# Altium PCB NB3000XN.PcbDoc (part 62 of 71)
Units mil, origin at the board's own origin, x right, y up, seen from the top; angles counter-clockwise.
Board outline 9527.56 x 6929.77 mil, 6 copper layers (Top Layer, GND+SHIELD, MidLayer1, MidLayer2, P2 - 3V3+5V0, Bottom Layer), stack 62.375 mil thick; 832 components, 1027 nets, 4655 pads, 4981 vias.
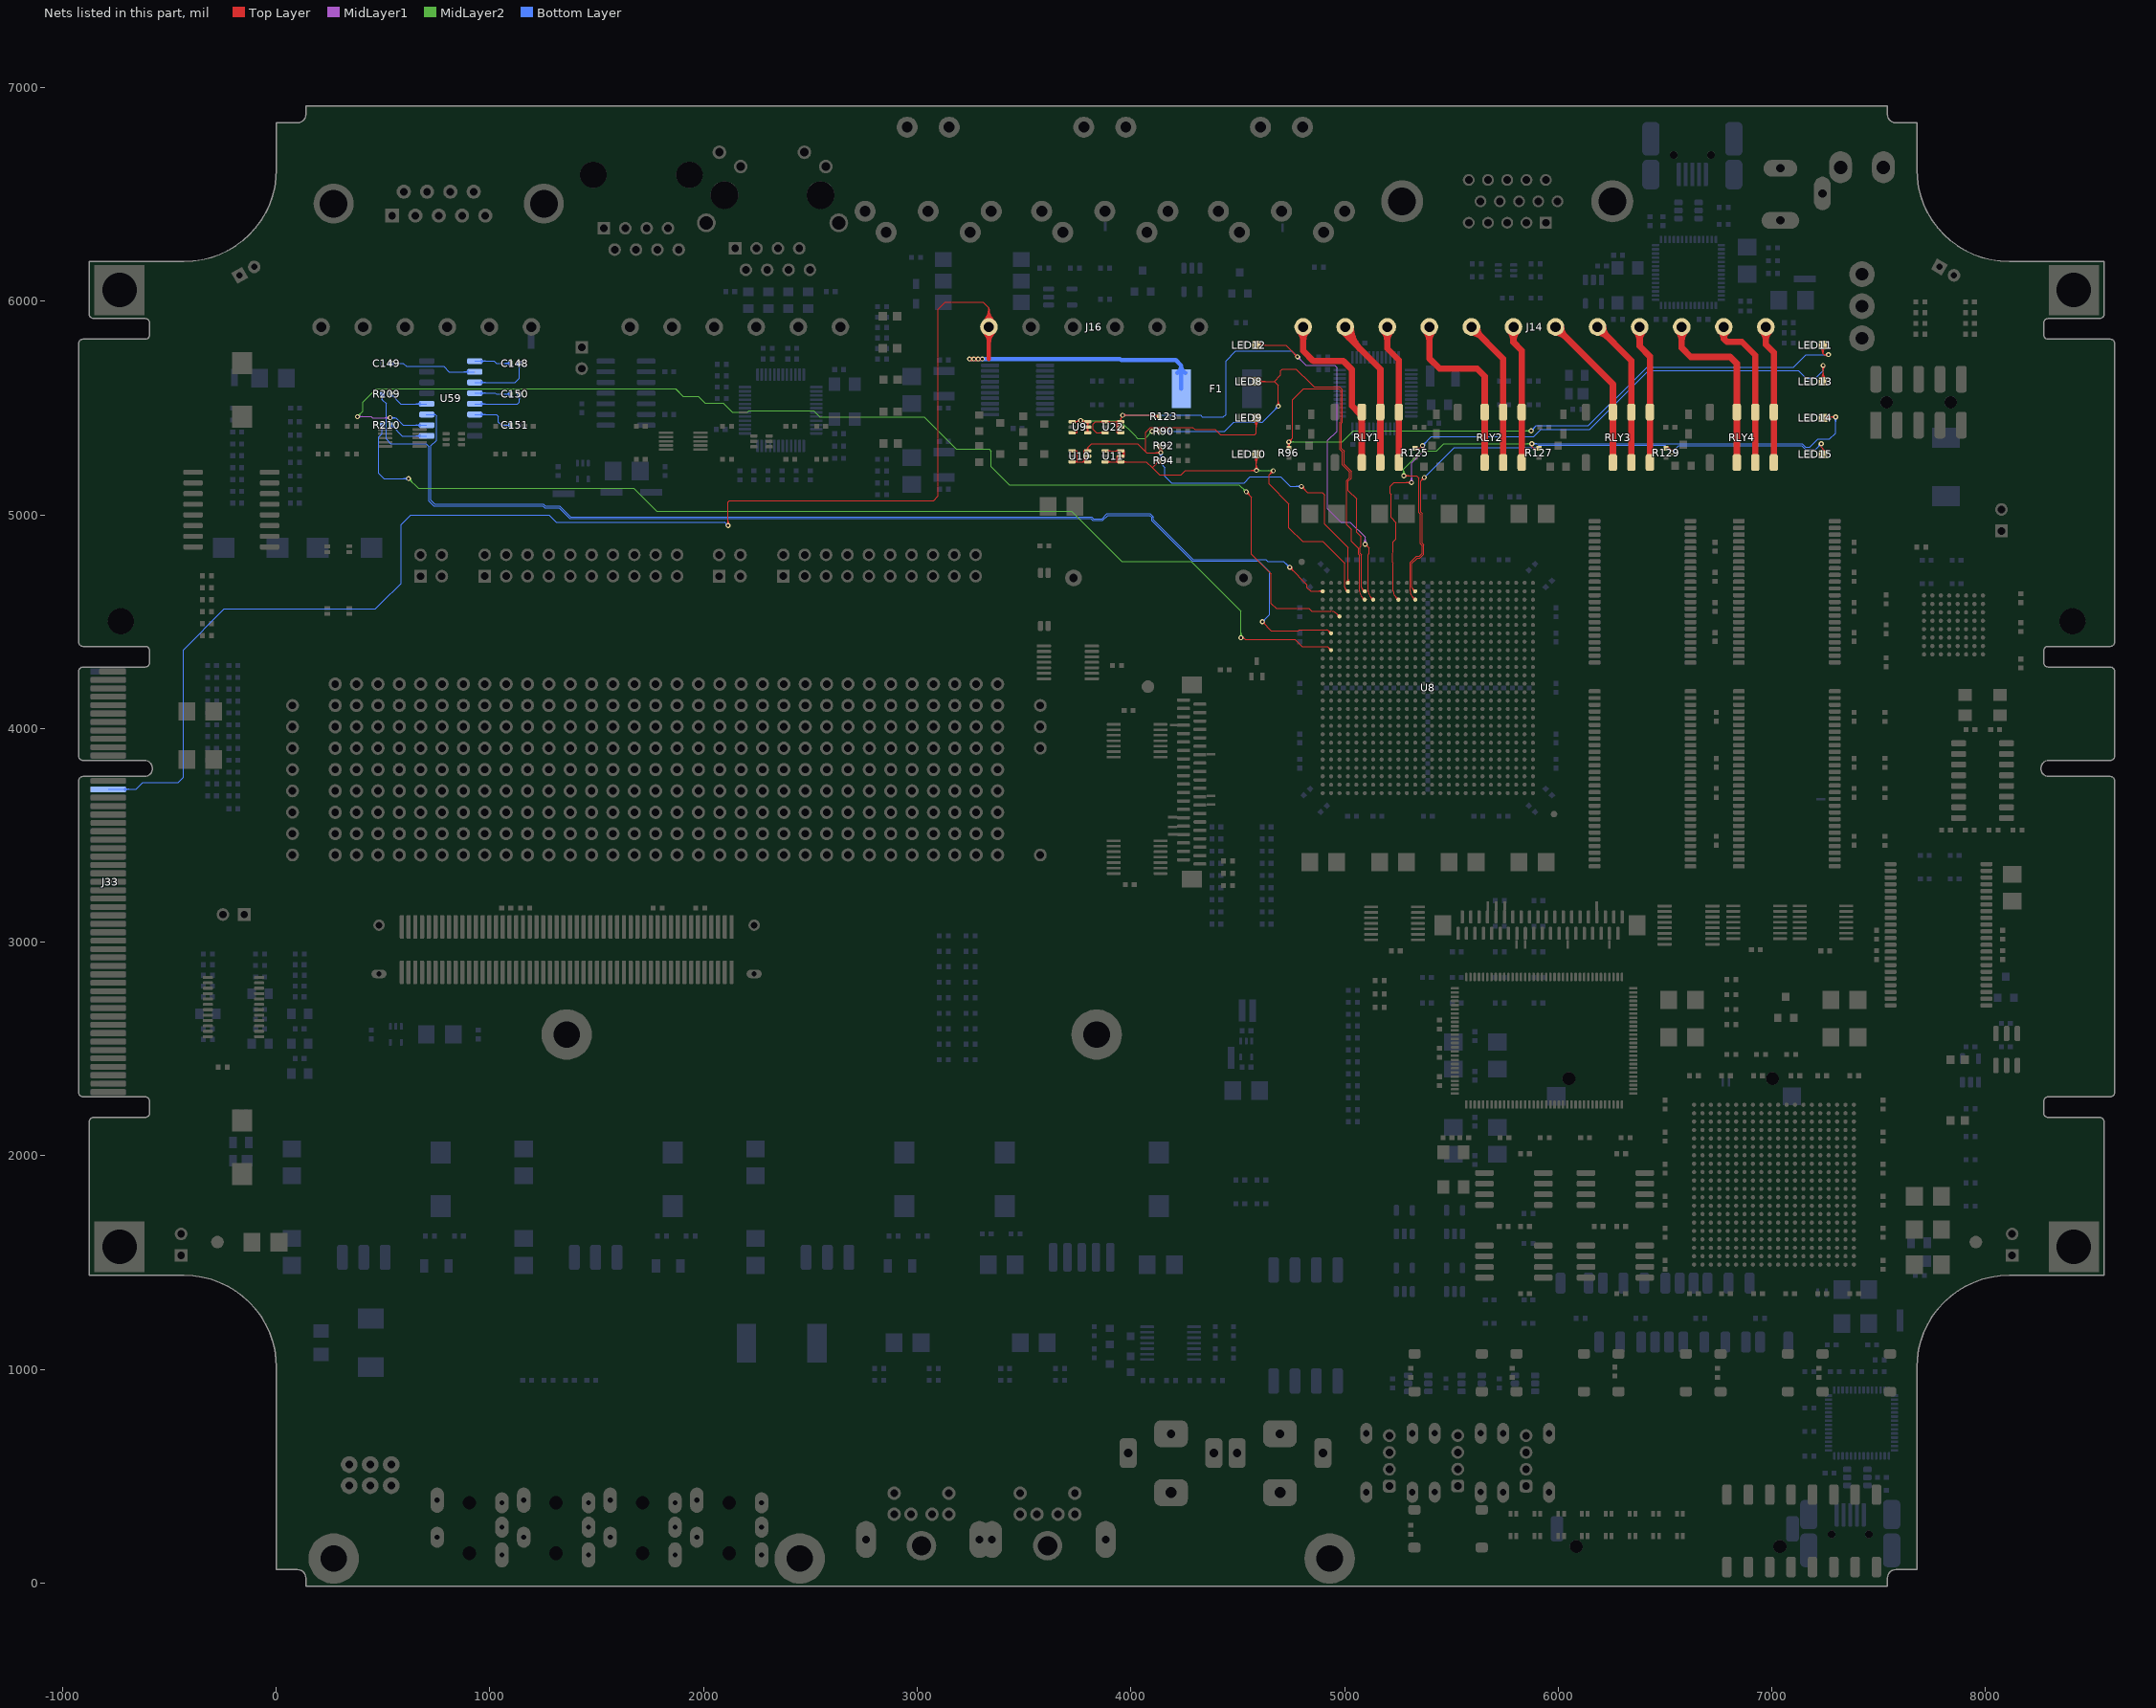
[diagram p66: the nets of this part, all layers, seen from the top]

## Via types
v1: diameter 23, hole 11.81, Top Layer to Bottom Layer, 3672 vias
v2: diameter 26, hole 11.81, Top Layer to Bottom Layer, 461 vias
v3: diameter 19, hole 11.81, Top Layer to Bottom Layer, tented both sides, 396 vias
v4: diameter 23.62, hole 11.81, Top Layer to Bottom Layer, 288 vias
v5: diameter 20, hole 11.81, Top Layer to Bottom Layer, 91 vias
v6: diameter 23, hole 11.81, Top Layer to Bottom Layer, tented both sides, 50 vias
v7: diameter 31, hole 11.81, Top Layer to Bottom Layer, 15 vias
v8: diameter 27.56, hole 11.81, Top Layer to Bottom Layer, tented both sides, 4 vias
v9: diameter 29, hole 11.81, Top Layer to Bottom Layer, 3 vias
v10: diameter 21, hole 11.81, Top Layer to Bottom Layer, 1 vias

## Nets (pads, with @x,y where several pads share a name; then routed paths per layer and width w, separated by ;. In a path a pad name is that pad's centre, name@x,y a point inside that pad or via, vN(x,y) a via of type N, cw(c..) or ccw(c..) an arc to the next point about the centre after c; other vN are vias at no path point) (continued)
PWM.PWM0: LED12.1 R123.1 U8.C7 U22.1 U22.3 U22.4 U22.5 U22.6 | length 4491.4
  Top Layer w4: U22.3@3866.99,5380.85 ccw(c3856.96,5370.82) 3856.96,5385 ccw(c3856.96,5399.18) U22.3@3866.99,5389.15 ; U22.1@3866.99,5432.03 ccw(c3856.96,5422) 3856.96,5436.18 ccw(c3856.96,5450.36) U22.1@3866.99,5440.33 ; U22.3@3880,5385 3839.23,5385 3823.52,5400.71 3823.52,5425.04 3834.66,5436.18 U22.1@3880,5436.18 3936.02,5436.18 ; U22.1@3893.01,5432.03 cw(c3903.04,5422) 3903.04,5436.18 cw(c3903.04,5450.36) U22.1@3893.01,5440.33 ; 3936.02,5383.79 cw(c3963.03,5383.79) U22.5@3947.38,5405.8 ; 3936.02,5388.38 ccw(c3946.19,5388.38) U22.4@3940.62,5379.88 ; 3936.02,5391.55 cw(c3957.52,5391.55) U22.5@3945.06,5409.06 ; 3936.02,5395.78 ccw(c3951.04,5395.78) U22.4@3942.81,5383.22 ; 3936.02,5399.3 cw(c3952.01,5399.3) U22.5@3942.74,5412.32 ; 3936.02,5403.19 ccw(c3955.89,5403.19) U22.4@3945,5386.57 ; 3936.02,5407.05 cw(c3946.49,5407.05) U22.5@3940.43,5415.58 ; 3936.02,5409.38 cw(c3963.03,5409.38) U22.6@3947.38,5431.39 ; 3936.02,5413.97 ccw(c3946.19,5413.97) U22.5@3940.62,5405.47 ; 3936.02,5417.14 cw(c3957.52,5417.14) U22.6@3945.06,5434.65 ; 3936.02,5421.37 ccw(c3951.04,5421.37) U22.5@3942.81,5408.81 ; 3936.02,5424.89 cw(c3952.01,5424.89) U22.6@3942.74,5437.91 ; 3936.02,5428.78 ccw(c3955.89,5428.78) U22.5@3945,5412.16 ; 3936.02,5432.64 cw(c3946.49,5432.64) U22.6@3940.43,5441.17 ; U22.4@3938.36,5383.27 ccw(c3936.02,5382.55) 3936.02,5385 ; U22.4@3938.36,5386.73 cw(c3936.02,5387.45) 3936.02,5385 ; U22.6@3939.82,5432.03 ccw(c3929.8,5422) 3929.8,5436.18 ccw(c3929.79,5450.36) U22.6@3939.82,5440.33 ; U22.4@3947.2,5389.91 cw(c3960.74,5410.59) 3936.02,5410.59 ; U22.5@3947.2,5415.5 cw(c3960.74,5436.18) 3936.02,5436.18 ; U22.6@3948.68,5440.33 ccw(c3938.65,5450.36) 3952.84,5450.36 ccw(c3967.01,5450.36) U22.6@3956.99,5440.33 ; U22.4@3952.83,5385 3936.02,5385 ; U22.5@3952.83,5410.59 3936.02,5410.59 ; 3952.84,5451.31 U22.6@3952.83,5436.18 3936.02,5436.18 ; 3952.86,5451.31 3961.52,5459.98 v1(3961.52,5466.71) 4127.11,5466.71 R123.1@4133.82,5460 ; v1@3965.41,5462.82 cw(c3974.8,5453.43) 3974.8,5466.71 cw(c3974.8,5479.99) v1@3965.41,5470.6 ; v1@3968.24,5459.99 cw(c3984.46,5443.77) 3984.46,5466.71 cw(c3984.46,5489.64) v1@3968.24,5473.43 ; 4096.31,5466.71 cw(c4096.31,5422.99) R123.1@4127.23,5453.9 ; 4105.97,5466.71 cw(c4105.97,5432.64) R123.1@4130.06,5456.73 ; 4115.63,5466.71 cw(c4115.63,5442.3) R123.1@4132.89,5459.56 ; LED12.1@4594.26,5788.44 cw(c4610.8,5771.91) 4610.8,5795.29 cw(c4610.8,5818.67) LED12.1@4594.26,5802.14 ; LED12.1@4597.09,5785.61 cw(c4620.45,5762.25) 4620.45,5795.29 cw(c4620.45,5828.33) LED12.1@4597.09,5804.97 ; LED12.1@4599.54,5788.95 cw(c4610,5783.49) 4610,5795.29 cw(c4610,5807.09) LED12.1@4599.54,5801.63 ; LED12.1@4599.92,5782.79 cw(c4630.11,5752.6) 4630.11,5795.29 cw(c4630.11,5837.99) LED12.1@4599.92,5807.8 ; LED12.1@4603.09,5787.1 cw(c4616.61,5780.04) 4616.61,5795.29 ; LED12.1@4603.09,5803.48 ccw(c4616.61,5810.54) 4616.61,5795.29 ; v1@4770.5,5740 ccw(c4747.56,5740) 4763.78,5756.22 ccw(c4780,5772.43) v1@4780,5749.5 ; v1@4774.5,5740 ccw(c4761.22,5740) 4770.61,5749.39 ccw(c4780,5758.78) v1@4780,5745.5 ; v1(4780,5740) 4724.71,5795.29 LED12.1@4587.42,5795.29 4616.61,5795.29 ; v1@5096.52,4853.54 cw(c5096.52,4830.61) 5112.74,4846.82 cw(c5128.96,4863.04) v1@5106.02,4863.04 ; v1@5096.52,4857.04 v1(5096.52,4863.04) 5115.19,4844.37 5115.19,4819.62 5110.23,4814.66 5110.23,4740.42 5110.23,4737 5110.23,4724.74 5110.23,4720 5110.23,4710 5110.23,4643.27 ; v1@5096.52,4857.54 cw(c5096.52,4844.26) 5105.91,4853.65 cw(c5115.3,4863.04) v1@5102.02,4863.04 ; 3936.02,5385 3936.02,5410.59 ; 3936.02,5410.59 cw(c3936.02,5408.14) U22.5@3938.36,5408.86 ; 3936.02,5410.59 ccw(c3936.02,5413.03) U22.5@3938.36,5412.32 ; 3936.02,5410.59 cw(c3936.02,5408.14) U22.5@3938.36,5408.86 ; 3936.02,5410.59 ccw(c3936.02,5413.03) U22.5@3938.36,5412.32 ; 3936.02,5410.59 cw(c3936.02,5408.15) U22.5@3938.36,5408.86 ; 3936.02,5410.59 ccw(c3936.02,5413.04) U22.5@3938.36,5412.32 ; 3936.02,5410.59 3936.02,5436.18 ; 3936.02,5436.18 cw(c3936.02,5433.74) 3938.36,5434.45 ccw(c3936.02,5433.74) 3936.02,5436.18 ; 3936.02,5436.18 ccw(c3936.02,5438.63) 3938.36,5437.91 cw(c3936.02,5438.63) 3936.02,5436.18 ; 5110.23,4643.27 ccw(c5148.91,4643.27) 5121.56,4615.92 ; 5110.23,4643.27 ccw(c5148.91,4643.27) 5121.56,4615.92 ; 5121.56,4615.92 cw(c5109.03,4603.39) 5126.75,4603.39 ccw(c5109.03,4603.39) 5121.56,4615.92 ; 5121.56,4615.92 ccw(c5134.09,4628.45) 5134.09,4610.73 cw(c5134.09,4628.45) 5121.56,4615.92
  MidLayer1 w4: v1@4780,5730.5 cw(c4780,5707.56) 4796.22,5723.78 cw(c4812.43,5740) v1@4789.5,5740 ; v1@4780,5734.5 cw(c4780,5721.22) 4789.39,5730.61 cw(c4798.78,5740) v1@4785.5,5740 ; v1(4780,5740) 4819.63,5700.37 4953.54,5700.37 4965.52,5688.39 4965.52,5392.35 4921.52,5348.35 4921.52,5027.63 4982.11,4967.04 5025.13,4967.04 5096.52,4895.65 v1(5096.52,4863.04) ; v1@5089.81,4869.76 ccw(c5073.59,4885.98) 5096.52,4885.98 ccw(c5119.46,4885.98) v1@5103.24,4869.76 ; v1@5092.64,4866.93 ccw(c5083.25,4876.32) 5096.52,4876.32 ccw(c5109.8,4876.32) v1@5100.41,4866.93
  Bottom Layer w4: v1(3961.52,5466.71) 4326.17,5466.71 4334.83,5458.04 4433.04,5458.04 4445,5470 4445,5721.71 4490,5766.71 4753.29,5766.71 v1(4780,5740) ; v1@3965.41,5462.82 cw(c3974.8,5453.43) 3974.8,5466.71 cw(c3974.8,5479.99) v1@3965.41,5470.6 ; v1@3968.24,5459.99 cw(c3984.46,5443.77) 3984.46,5466.71 cw(c3984.46,5489.64) v1@3968.24,5473.43 ; v1@4770.5,5740 ccw(c4747.56,5740) 4763.78,5756.22 ccw(c4780,5772.43) v1@4780,5749.5 ; v1@4774.5,5740 ccw(c4761.22,5740) 4770.61,5749.39 ccw(c4780,5758.78) v1@4780,5745.5
PWM.PWM1: LED8.1 R90.1 U8.B6 U9.1 U9.3 U9.4 U9.5 U9.6 | length 3726.6
  Top Layer w4: U9.3@3725,5385 3746.86,5385 ; U9.1@3725,5436.18 3746.86,5436.18 ; U9.3@3738.27,5381.12 cw(c3746.86,5373.56) 3746.86,5385 ; U9.3@3738.27,5388.88 ccw(c3746.86,5396.44) 3746.86,5385 ; U9.1@3738.27,5432.3 cw(c3746.86,5424.74) 3746.86,5436.18 ; U9.1@3738.27,5440.06 ccw(c3746.86,5447.62) 3746.86,5436.18 ; 3748.48,5437.8 cw(c3758.11,5428.17) v1@3764.19,5440.37 ; 3752.41,5441.74 cw(c3760.73,5433.42) v1@3765.97,5443.95 ; v1@3765.99,5442.69 ccw(c3780.28,5455.11) 3780.28,5436.18 ; v1@3769.01,5445.32 ccw(c3789.06,5462.75) U9.6@3789.06,5436.18 ; v1@3772.03,5447.94 ccw(c3797.83,5470.38) U9.6@3797.83,5436.18 ; U9.6@3784.82,5432.03 ccw(c3774.8,5422) 3774.8,5436.18 ccw(c3774.79,5450.36) U9.6@3784.82,5440.33 ; U9.4@3793.68,5389.15 ccw(c3783.65,5399.18) 3797.84,5399.18 ccw(c3812.01,5399.18) U9.4@3801.99,5389.15 ; U9.5@3793.68,5406.44 cw(c3783.65,5396.41) 3797.84,5396.41 cw(c3812.01,5396.41) U9.5@3801.99,5406.44 ; U9.5@3793.68,5414.74 ccw(c3783.65,5424.77) 3797.84,5424.77 ccw(c3812.01,5424.77) U9.5@3801.99,5414.74 ; U9.6@3793.68,5432.03 cw(c3783.65,5422) 3797.84,5422 ; U9.4@3797.83,5385 U9.5@3797.83,5410.59 U9.6@3797.83,5436.18 ; 3797.84,5422 cw(c3812.01,5422) U9.6@3801.99,5432.03 ; v1(4099.19,5391.37) 4115.19,5391.37 ; v1@4107.53,5386.83 cw(c4115.19,5382.65) 4115.19,5391.37 ; v1@4107.53,5395.92 ccw(c4115.19,5400.1) 4115.19,5391.37 ; R90.1@4126.27,5385.71 ccw(c4115.19,5377.71) 4115.19,5391.37 ; R90.1@4126.29,5386.17 ccw(c4115.48,5378.29) 4115.48,5391.67 ; R90.1@4126.29,5397.16 cw(c4115.48,5405.05) 4115.48,5391.67 ; R90.1@4126.46,5396.89 cw(c4115.19,5405.64) 4115.19,5391.37 ; LED8.1@4587.42,5624.9 4671.52,5624.9 ; LED8.1@4594.26,5618.06 cw(c4610.8,5601.52) 4610.8,5624.9 cw(c4610.8,5648.29) LED8.1@4594.26,5631.75 ; LED8.1@4597.09,5615.23 cw(c4620.45,5591.87) 4620.45,5624.9 cw(c4620.45,5657.94) LED8.1@4597.09,5634.58 ; LED8.1@4599.92,5612.4 cw(c4630.11,5582.21) 4630.11,5624.9 cw(c4630.11,5667.6) LED8.1@4599.92,5637.41 ; v1@4683.47,5515.09 ccw(c4667.26,5531.31) 4690.19,5531.31 ccw(c4713.13,5531.31) v1@4696.91,5515.09 ; v1@4686.3,5512.26 ccw(c4676.91,5521.65) 4690.19,5521.65 ccw(c4703.47,5521.65) v1@4694.08,5512.26 ; v1(4690.19,5508.37) 4690.19,5606.24 4671.52,5624.9 ; 3746.86,5385 3748.52,5386.67 3748.52,5434.51 3746.86,5436.18 ; 3746.86,5436.18 3752.38,5441.71 v1(3764.86,5441.71) 3764.86,5441.51 3770.19,5436.18 U9.6@3797.83,5436.18 ; 4115.19,5391.37 4115.48,5391.67 ; 4115.19,5391.37 4133.53,5391.37 R90.1@4133.82,5391.67 4115.48,5391.67 ; 4671.52,5624.9 4701.86,5655.24 4701.86,5675.04 4710.19,5683.37 4773.52,5683.37 4839.69,5617.2 4856.86,5600.04 4975.52,5600.04 4990.19,5585.37 4990.19,5465 4990.19,5433.88 4986,5429.69 4986,5310.86 4997.86,5299 4997.86,5238 5006.86,5229 5031.86,5204 5031.86,5172.06 5017.5,5157.7 5017.5,5125 ; 5017.5,5114.04 5056.7,5074.85 5056.7,4919.56 5077.52,4898.73 5077.52,4853.37 5073.52,4849.37 5073.52,4819.59 5079.22,4813.89 5079.22,4724.74 5079.22,4720 5079.22,4710 5079.22,4662.47 ; 5017.5,5114.04 5017.5,5125 ; 5017.5,5114.04 5017.5,5125 ; 5079.22,4662.47 ccw(c5089.37,4662.47) 5082.19,4655.29 ; 5079.22,4662.47 ccw(c5089.37,4662.47) 5082.19,4655.29 ; 5082.19,4655.29 ccw(c5094.72,4667.83) 5094.72,4650.1 cw(c5094.72,4667.83) 5082.19,4655.29 ; 5082.19,4655.29 cw(c5069.66,4642.76) 5087.38,4642.76 ccw(c5069.66,4642.76) 5082.19,4655.29
  MidLayer2 w4: v1(3764.86,5441.71) 3948.52,5441.71 4015.19,5375.04 ; v1@3768.75,5437.82 cw(c3778.14,5428.43) 3778.14,5441.71 cw(c3778.14,5454.99) v1@3768.75,5445.6 ; v1@3771.57,5434.99 cw(c3787.79,5418.77) 3787.79,5441.71 cw(c3787.79,5464.64) v1@3771.57,5448.43 ; v1@4089.69,5391.37 cw(c4066.76,5391.37) 4082.97,5375.16 cw(c4099.19,5358.94) v1@4099.19,5381.87 ; v1@4093.69,5391.37 cw(c4080.41,5391.37) 4089.8,5381.99 cw(c4099.19,5372.6) v1@4099.19,5385.87 ; v1(4099.19,5391.37) 4066.19,5358.37 4031.86,5358.37 ; 4015.19,5375.04 4031.86,5358.37 ; 4015.19,5375.04 4031.86,5358.37
  Bottom Layer w4: v1(4099.19,5391.37) 4438.52,5391.37 4480.52,5433.37 4615.19,5433.37 v1(4690.19,5508.37) ; v1@4103.08,5387.49 cw(c4112.47,5378.1) 4112.47,5391.37 cw(c4112.47,5404.65) v1@4103.08,5395.26 ; v1@4105.91,5384.66 cw(c4122.13,5368.44) 4122.13,5391.37 cw(c4122.13,5414.31) v1@4105.91,5398.09 ; v1@4680.69,5508.37 cw(c4657.76,5508.37) 4673.97,5492.16 cw(c4690.19,5475.94) v1@4690.19,5498.87 ; v1@4684.69,5508.37 cw(c4671.41,5508.37) 4680.8,5498.99 cw(c4690.19,5489.6) v1@4690.19,5502.87
PWM.PWM2: LED9.1 R92.1 U8.A4 U10.1 U10.3 U10.4 U10.5 U10.6 | length 3714.7
  Top Layer w4: U10.3@3725,5248.82 3748.52,5248.82 ; U10.1@3725,5300 3746.86,5300 ; U10.3@3738.01,5244.67 cw(c3748.04,5234.64) 3748.04,5248.82 cw(c3748.04,5263) U10.3@3738.01,5252.97 ; U10.1@3738.27,5296.12 cw(c3746.86,5288.56) 3746.86,5300 ; U10.1@3738.27,5303.88 ccw(c3746.86,5311.44) 3746.86,5300 ; 3780.19,5247.35 cw(c3806.61,5247.35) U10.5@3792.18,5269.49 ; 3780.19,5248.82 3780.19,5274.41 ; 3780.19,5253.46 ccw(c3791.7,5253.46) U10.4@3785.88,5243.53 ; 3780.19,5254.74 cw(c3801.8,5254.74) U10.5@3790,5272.84 ; 3780.19,5260.44 ccw(c3795.79,5260.44) U10.4@3787.9,5246.98 ; 3780.19,5262.12 cw(c3796.99,5262.12) U10.5@3787.82,5276.19 ; 3780.19,5267.43 ccw(c3799.88,5267.43) U10.4@3789.92,5250.44 ; 3780.19,5269.5 cw(c3792.18,5269.5) U10.5@3785.63,5279.54 ; 3780.19,5272.94 cw(c3806.61,5272.94) U10.6@3792.18,5295.08 ; 3780.19,5279.05 ccw(c3791.7,5279.05) U10.5@3785.88,5269.12 ; 3780.19,5280.33 cw(c3801.8,5280.33) U10.6@3790,5298.43 ; 3780.19,5286.03 ccw(c3795.79,5286.03) U10.5@3787.9,5272.58 ; 3780.19,5287.71 cw(c3796.99,5287.71) U10.6@3787.82,5301.78 ; 3780.19,5293.02 ccw(c3799.89,5293.02) U10.5@3789.92,5276.03 ; 3780.19,5295.09 cw(c3792.18,5295.09) U10.6@3785.63,5305.13 ; 3780.19,5300 ccw(c3803.98,5300) U10.5@3791.95,5279.48 ; U10.6@3783.55,5297.75 ccw(c3780.19,5296.37) 3780.19,5300 ; U10.6@3783.55,5302.24 cw(c3780.19,5303.63) 3780.19,5300 ; U10.4@3784.82,5244.67 ccw(c3774.8,5234.64) 3774.8,5248.82 ccw(c3774.79,5263) U10.4@3784.82,5252.97 ; U10.4@3791.95,5253.89 cw(c3803.98,5274.41) 3780.19,5274.41 ; U10.6@3793.68,5304.15 ccw(c3783.65,5314.18) 3797.84,5314.18 ccw(c3812.01,5314.18) U10.6@3801.99,5304.15 ; U10.4@3797.83,5248.82 3748.52,5248.82 ; U10.5@3797.83,5274.41 3780.19,5274.41 ; R92.1@4128.15,5315.44 cw(c4109.48,5291.06) v1@4140.19,5291.06 ; R92.1@4130.59,5318.62 cw(c4115.69,5299.16) v1@4140.19,5299.16 ; R92.1@4133.02,5321.79 cw(c4121.89,5307.27) 4140.19,5307.27 ; v1@4133.47,5284.99 ccw(c4117.26,5268.77) 4117.26,5291.71 ccw(c4117.26,5314.64) 4133.47,5298.43 ccw(c4117.26,5314.64) 4140.19,5314.64 ccw(c4163.13,5314.64) v1@4146.91,5298.43 ; v1@4136.3,5287.82 ccw(c4126.91,5278.43) 4126.91,5291.71 ccw(c4126.91,5304.99) 4136.3,5295.6 ccw(c4126.91,5304.99) 4140.19,5304.99 ccw(c4153.47,5304.99) v1@4144.08,5295.6 ; R92.1@4140.19,5316.96 v1(4140.19,5291.71) 4073.29,5291.71 4070,5295 ; LED9.1@4574.91,5442.01 cw(c4544.72,5411.82) 4587.42,5411.82 cw(c4630.11,5411.82) LED9.1@4599.92,5442.01 ; LED9.1@4577.74,5444.84 cw(c4554.38,5421.48) 4587.42,5421.48 cw(c4620.45,5421.48) LED9.1@4597.09,5444.84 ; LED9.1@4580.57,5447.67 cw(c4564.03,5431.14) 4587.42,5431.14 cw(c4610.8,5431.14) LED9.1@4594.26,5447.67 ; LED9.1@4587.42,5454.52 4587.42,5382.42 4579.71,5374.71 4418.46,5374.71 4393.17,5400 4299.71,5400 4290,5409.71 4092.77,5409.71 4070,5386.93 4070,5295 ; v1@4798.52,5123.87 cw(c4798.52,5100.94) 4814.74,5117.16 cw(c4830.96,5133.37) v1@4808.02,5133.37 ; v1@4798.52,5127.87 cw(c4798.52,5114.6) 4807.91,5123.99 cw(c4817.3,5133.37) v1@4804.02,5133.37 ; v1(4798.52,5133.37) 4826.9,5105 4895,5105 4907.19,5092.81 4907.19,4957.06 4906.86,4956.73 5015.98,4847.6 5015.98,4720 5015.98,4710 U8.A4@5015.98,4682.13 ; U8.A4@5010.68,4687.43 ccw(c4997.88,4700.23) 5015.98,4700.23 ccw(c5034.09,4700.23) U8.A4@5021.29,4687.43 ; U8.A4@5010.79,4687.32 ccw(c4998.26,4699.85) 5015.98,4699.85 ccw(c5033.71,4699.85) U8.A4@5021.18,4687.32 ; 3746.86,5300 3748.52,5298.33 3748.52,5248.82 ; 3780.19,5274.41 cw(c3780.19,5270.77) U10.5@3783.55,5272.16 ; 3780.19,5274.41 ccw(c3780.19,5278.04) U10.5@3783.55,5276.65 ; 3780.19,5274.41 cw(c3780.19,5270.78) U10.5@3783.55,5272.16 ; 3780.19,5274.41 ccw(c3780.19,5278.04) U10.5@3783.55,5276.65 ; 3780.19,5274.41 cw(c3780.19,5270.78) U10.5@3783.55,5272.16 ; 3780.19,5274.41 ccw(c3780.19,5278.04) U10.5@3783.55,5276.65 ; 3780.19,5274.41 3780.19,5300 ; 3780.19,5300 U10.6@3797.83,5300 3797.84,5314.35 3816.86,5333.37 4031.63,5333.37 4070,5295
  Bottom Layer w4: v1@4133.47,5284.99 cw(c4117.26,5268.77) 4140.19,5268.77 cw(c4163.13,5268.77) v1@4146.91,5284.99 ; v1@4136.3,5287.82 cw(c4126.91,5278.43) 4140.19,5278.43 cw(c4153.47,5278.43) v1@4144.08,5287.82 ; v1(4140.19,5291.71) 4140.19,5241.71 4159.82,5222.08 4159.82,5180.18 4189.81,5150.19 4530.19,5150.19 4557.81,5177.81 4701.09,5177.81 4714.49,5164.41 4745.52,5133.37 v1(4798.52,5133.37) ; v1@4791.81,5126.66 ccw(c4775.59,5110.44) 4775.59,5133.37 ccw(c4775.59,5156.31) v1@4791.81,5140.09 ; v1@4794.64,5129.49 ccw(c4785.25,5120.1) 4785.25,5133.37 ccw(c4785.25,5146.65) v1@4794.64,5137.26
PWM.PWM3: LED10.1 R94.1 U8.B4 U11.1 U11.3 U11.4 U11.5 U11.6 | length 2931.5
  Top Layer w4: U11.3@3880,5248.82 U11.4@3952.83,5248.82 4072.34,5248.82 ; U11.1@3880,5300 U11.6@3952.83,5300 3970.9,5300 ; U11.3@3893.01,5244.67 cw(c3903.04,5234.64) 3903.04,5248.82 cw(c3903.04,5263) U11.3@3893.01,5252.97 ; U11.1@3893.01,5295.85 cw(c3903.04,5285.82) 3903.04,5300 cw(c3903.04,5314.18) U11.1@3893.01,5304.15 ; 3935.19,5247.35 cw(c3961.61,5247.35) U11.5@3947.18,5269.49 ; 3935.19,5248.82 3935.19,5274.41 ; 3935.19,5253.46 ccw(c3946.7,5253.46) U11.4@3940.88,5243.53 ; 3935.19,5254.74 cw(c3956.8,5254.74) U11.5@3945,5272.84 ; 3935.19,5260.44 ccw(c3950.79,5260.44) U11.4@3942.9,5246.98 ; 3935.19,5262.12 cw(c3951.99,5262.12) U11.5@3942.82,5276.19 ; 3935.19,5267.43 ccw(c3954.88,5267.43) U11.4@3944.92,5250.44 ; 3935.19,5269.5 cw(c3947.18,5269.5) U11.5@3940.63,5279.54 ; U11.5@3938.55,5272.16 ccw(c3935.19,5270.77) 3935.19,5274.41 ; U11.5@3938.55,5276.65 cw(c3935.19,5278.04) 3935.19,5274.41 ; U11.4@3939.82,5244.67 ccw(c3929.8,5234.64) 3929.8,5248.82 ccw(c3929.79,5263) U11.4@3939.82,5252.97 ; U11.6@3939.82,5295.85 ccw(c3929.8,5285.82) 3929.8,5300 ccw(c3929.79,5314.18) U11.6@3939.82,5304.15 ; U11.4@3946.95,5253.89 cw(c3958.98,5274.41) 3935.19,5274.41 ; U11.6@3958.58,5295.02 cw(c3944.71,5272.8) 3970.9,5272.8 ; U11.5@3958.85,5279.55 ccw(c3947.52,5300) 3970.9,5300 ; U11.6@3960.7,5298.41 cw(c3949.22,5280.02) 3970.9,5280.02 ; U11.5@3960.79,5276.05 ccw(c3951.28,5293.21) 3970.9,5293.21 ; U11.5@3962.72,5272.55 ccw(c3955.04,5286.42) 3970.9,5286.42 ; U11.6@3962.82,5301.8 cw(c3953.72,5287.23) 3970.9,5287.23 ; U11.5@3964.66,5269.05 ccw(c3958.8,5279.64) 3970.9,5279.64 ; U11.6@3964.94,5305.2 cw(c3958.22,5294.45) 3970.9,5294.45 ; U11.4@3965.85,5244.67 cw(c3975.87,5234.64) 3975.87,5248.82 cw(c3975.87,5263) U11.4@3965.85,5252.97 ; U11.6@3967.02,5297.52 cw(c3970.9,5295.72) 3970.9,5300 ; U11.6@3967.02,5302.47 ccw(c3970.9,5304.28) 3970.9,5300 ; 4117.07,5238.25 cw(c4133.82,5221.5) R94.1@4133.82,5245.19 ; 4118.26,5239.44 ccw(c4103.19,5254.51) R94.1@4124.5,5254.51 ; R94.1@4123.9,5245.08 cw(c4133.82,5235.16) R94.1@4133.82,5249.19 ; R94.1@4125.09,5246.27 ccw(c4116.85,5254.51) R94.1@4128.5,5254.51 ; R94.1@4133.82,5255 4099.99,5221.17 ; LED10.1@4574.91,5271.63 cw(c4544.72,5241.44) 4587.42,5241.44 cw(c4630.11,5241.43) LED10.1@4599.92,5271.63 ; LED10.1@4577.74,5274.45 cw(c4554.38,5251.09) 4587.42,5251.09 cw(c4620.45,5251.09) LED10.1@4597.09,5274.45 ; LED10.1@4580.57,5277.28 cw(c4564.03,5260.75) 4587.42,5260.75 cw(c4610.8,5260.75) LED10.1@4594.26,5277.28 ; v1@4581.47,5201.66 ccw(c4565.26,5185.44) 4565.26,5208.37 ccw(c4565.26,5231.31) 4581.47,5215.09 ccw(c4567.13,5229.44) 4587.42,5229.44 ; v1@4584.3,5204.49 ccw(c4574.91,5195.1) 4574.91,5208.37 ccw(c4574.91,5221.65) v1@4584.3,5212.26 ; 4587.42,5223.52 ccw(c4603.34,5223.52) v1@4592.08,5212.26 ; 4587.42,5233.18 ccw(c4613,5233.18) v1@4594.91,5215.09 ; LED10.1@4587.42,5284.13 4587.42,5209.1 v1@4588.14,5208.37 ; v1(4588.19,5208.37) v1@4588.14,5208.37 ; v1@4657.36,5206.71 cw(c4634.42,5206.71) 4650.64,5190.49 cw(c4666.86,5174.27) v1@4666.86,5197.21 ; v1@4661.36,5206.71 cw(c4648.08,5206.71) 4657.47,5197.32 cw(c4666.86,5187.93) v1@4666.86,5201.21 ; v1(4666.86,5206.71) 4648.19,5188.04 4648.19,5144.02 4740.19,5052.02 4740.19,5000 4740.19,4950.04 4740.19,4939.34 4803.82,4875.71 4898.11,4875.71 4899.61,4874.21 4899.73,4874.21 5000.48,4773.46 5000.48,4724.74 5000.48,4720 5000.48,4710 5000.48,4662.47 ; 3935.19,5274.41 U11.5@3952.83,5274.41 3970.9,5274.41 ; U11.5@3967.02,5271.93 cw(c3970.9,5270.13) 3970.9,5274.41 ; U11.5@3967.02,5271.93 cw(c3970.9,5270.13) 3970.9,5274.41 ; U11.5@3967.02,5271.93 cw(c3970.9,5270.13) 3970.9,5274.41 ; U11.5@3967.02,5276.88 ccw(c3970.9,5278.69) 3970.9,5274.41 ; U11.5@3967.02,5276.88 ccw(c3970.9,5278.69) 3970.9,5274.41 ; U11.5@3967.02,5276.88 ccw(c3970.9,5278.69) 3970.9,5274.41 ; 3970.9,5274.41 3970.9,5300 ; 4072.34,5248.82 4099.99,5221.17 ; 4072.34,5248.82 4099.99,5221.17 ; 4099.99,5221.17 4133.82,5187.34 4235,5187.34 4256.03,5208.37 v1@4588.14,5208.37 ; 5000.48,4662.47 ccw(c5010.63,4662.47) 5003.45,4655.29 ; 5000.48,4662.47 ccw(c5010.63,4662.47) 5003.45,4655.29 ; 5003.45,4655.29 ccw(c5015.98,4667.83) 5015.98,4650.1 cw(c5015.98,4667.83) 5003.45,4655.29 ; 5003.45,4655.29 cw(c4990.92,4642.76) 5008.64,4642.76 ccw(c4990.92,4642.76) 5003.45,4655.29
  MidLayer2 w4: v1(4588.19,5208.37) 4589.86,5206.71 v1(4666.86,5206.71) ; v1@4592.08,5212.26 ccw(c4605.49,5225.68) 4605.49,5206.71 ; v1@4594.91,5201.66 cw(c4607.1,5189.46) 4607.1,5206.71 ; v1@4594.91,5215.09 ccw(c4615.15,5235.33) 4615.15,5206.71 ; v1@4660.14,5199.99 ccw(c4643.92,5183.77) 4643.92,5206.71 ccw(c4643.92,5229.64) v1@4660.14,5213.43 ; v1@4662.97,5202.82 ccw(c4653.58,5193.43) 4653.58,5206.71 ccw(c4653.58,5219.99) v1@4662.97,5210.6
PWMPWR: F1.2 J16.1 J33.B13 | length 8596
  Top Layer w4: v1@2108.47,4956.76 ccw(c2092.26,4972.98) 2115.19,4972.98 ccw(c2138.13,4972.98) v1@2121.91,4956.76 ; v1@2111.3,4953.93 ccw(c2101.91,4963.32) 2115.19,4963.32 ccw(c2128.47,4963.32) v1@2119.08,4953.93 ; v1(2115.19,4950.04) 2115.19,5060.19 2122,5067 3077,5067 3098.19,5088.19 3098.19,5963.19 3132.06,5997.06 3307.94,5997.06 3335.92,5969.08 ; J16.1@3309.42,5909.08 ccw(c3254.75,5969.08) 3335.92,5969.08 ; J16.1@3312.12,5906.13 ccw(c3263,5960.02) 3335.92,5960.02 ccw(c3408.83,5960.02) J16.1@3359.72,5906.13 ; J16.1@3314.81,5903.17 ccw(c3271.26,5950.96) 3335.92,5950.96 ccw(c3400.58,5950.96) J16.1@3357.03,5903.17 ; J16.1@3317.5,5900.21 ccw(c3279.51,5941.91) 3335.92,5941.91 ccw(c3392.33,5941.91) J16.1@3354.33,5900.21 ; J16.1@3320.2,5897.26 ccw(c3287.76,5932.85) 3335.92,5932.85 ccw(c3384.07,5932.85) J16.1@3351.64,5897.26 ; J16.1@3322.89,5894.3 ccw(c3296.02,5923.79) 3335.92,5923.79 ccw(c3375.82,5923.79) J16.1@3348.94,5894.3 ; J16.1@3335.92,5880.01 3335.92,5969.08 ; J16.1@3362.41,5909.08 cw(c3417.09,5969.08) 3335.92,5969.08
  Top Layer w20: v1(3245,5730) v1@3290.19,5730 ; J16.1@3313.76,5857.85 cw(c3260.26,5804.35) 3335.92,5804.35 cw(c3411.58,5804.35) J16.1@3358.08,5857.85 ; 3335.92,5730 J16.1@3335.92,5880.01
  Bottom Layer w4: J33.B13@-785.98,3715.85 -655,3715.85 -623.63,3747.22 -459.09,3747.22 -435,3771.31 -435,4368.89 -243.85,4560.04 303.39,4560.04 ; J33.B13@-711.58,3710.35 cw(c-698.3,3697.07) -698.3,3715.85 cw(c-698.3,3734.63) J33.B13@-711.58,3721.35 ; J33.B13@-708.76,3707.52 cw(c-688.65,3687.41) -688.65,3715.85 cw(c-688.65,3744.29) J33.B13@-708.76,3724.18 ; 303.43,4560 465.15,4560 493.84,4588.69 585.21,4680.06 585.21,4953.9 630.5,4999.19 1277.52,4999.19 1310,4966.71 2098.52,4966.71 v1(2115.19,4950.04) ; v1@2105.69,4950.04 ccw(c2082.76,4950.04) 2098.97,4966.26 ccw(c2115.19,4982.48) v1@2115.19,4959.54 ; v1@2109.69,4950.04 ccw(c2096.41,4950.04) 2105.8,4959.43 ccw(c2115.19,4968.82) v1@2115.19,4955.54
  Bottom Layer w20: v1(3245,5730) 3949.17,5730 3954.63,5724.54 4210.46,5724.54 4235.75,5699.25 ; F1.2@4216.92,5665.11 ccw(c4195.38,5699.25) 4235.75,5699.25 ; F1.2@4235.75,5590 4235.75,5699.25 ; F1.2@4254.57,5665.11 cw(c4276.12,5699.25) 4235.75,5699.25
  other v1: 3265,5730 3285,5730 3305,5730
RELAY.RELAY0: LED11.1 R96.1 U8.C6 | length 5062.8
  Top Layer w4: v1@4732.47,5334.99 cw(c4714.3,5316.82) R96.1@4740,5316.82 ; R96.1@4733.41,5317.77 ccw(c4717.5,5333.68) 4740,5333.68 ccw(c4762.5,5333.68) R96.1@4746.59,5317.77 ; v1@4735.3,5337.82 cw(c4723.96,5326.47) 4740,5326.47 ; R96.1@4736.24,5314.94 ccw(c4727.16,5324.02) 4740,5324.02 ccw(c4752.84,5324.02) R96.1@4743.76,5314.94 ; v1@4739.19,5347.21 ccw(c4739.19,5360.49) 4748.58,5351.1 ccw(c4757.97,5341.71) v1@4744.69,5341.71 ; v1@4739.19,5351.21 ccw(c4739.19,5374.14) 4755.41,5357.93 ccw(c4771.63,5341.71) v1@4748.69,5341.71 ; R96.1@4740,5311.18 4740,5341.04 4739.33,5341.71 v1(4739.19,5341.71) 4756.86,5359.37 4756.86,5540.04 4808.52,5591.71 4950,5591.71 4966.86,5591.71 4972.54,5591.71 4982.19,5582.06 4982.19,5576.37 4982.19,5437.19 ; R96.1@4740,5320.73 cw(c4760.17,5320.73) v1@4745.91,5334.99 ; 4982.19,5570 4982.19,5437.19 ; 5065,4844 5065,4843.84 ; LED11.1@7227.37,5782.07 cw(c7204.06,5755.88) 7239.12,5755.88 ; LED11.1@7230.03,5785.06 cw(c7211.99,5764.79) 7239.12,5764.79 cw(c7266.25,5764.79) LED11.1@7248.22,5785.06 ; LED11.1@7232.69,5788.05 cw(c7219.92,5773.7) 7239.12,5773.7 cw(c7258.32,5773.7) LED11.1@7245.56,5788.05 ; LED11.1@7239.12,5795.28 7239.12,5755.88 ; LED11.1@7250.88,5782.07 ccw(c7274.18,5755.88) 7239.12,5755.88 ; v1@7257.88,5743.97 ccw(c7244.96,5733.25) 7244.96,5750.04 ; v1@7257.88,5756.11 cw(c7244.96,5766.83) 7244.96,5750.04 ; v1@7260.96,5746.53 ccw(c7253.48,5740.32) 7253.48,5750.04 ccw(c7253.48,5759.76) v1@7260.96,5753.55 ; v1(7265.19,5750.04) 7244.96,5750.04 ; 4982.19,5437.19 4978,5433 4978,5306.88 4989.86,5295.02 4989.86,5234.69 5023.52,5201.02 5023.52,5175.04 5010.19,5161.71 5009.5,5161.02 5009.5,4955.73 5010.19,4955.04 5031.86,4933.37 5031.86,4876.98 5065,4843.84 ; 5065,4843.84 5065,4816.8 5070.86,4810.93 5070.86,4724.74 5070.86,4720 5070.86,4710 5070.86,4643.27 ; 5070.86,4643.27 ccw(c5109.54,4643.27) 5082.19,4615.92 ; 5070.86,4643.27 ccw(c5109.54,4643.27) 5082.19,4615.92 ; 5082.19,4615.92 cw(c5069.66,4603.39) 5087.38,4603.39 ccw(c5069.66,4603.39) 5082.19,4615.92 ; 5082.19,4615.92 ccw(c5094.72,4628.45) 5094.72,4610.73 cw(c5094.72,4628.45) 5082.19,4615.92 ; 7239.12,5755.88 7244.96,5750.04
  MidLayer2 w4: v1(4739.19,5341.71) 4990.19,5341.71 5041.86,5393.37 v1(5873.52,5393.37) ; v1@4743.08,5337.82 cw(c4752.47,5328.43) 4752.47,5341.71 cw(c4752.47,5354.99) v1@4743.08,5345.6 ; v1@4745.91,5334.99 cw(c4762.13,5318.77) 4762.13,5341.71 cw(c4762.13,5364.64) v1@4745.91,5348.43 ; v1@5866.81,5386.66 ccw(c5850.59,5370.44) 5850.59,5393.37 ccw(c5850.59,5416.31) v1@5866.81,5400.09 ; v1@5869.64,5389.49 ccw(c5860.25,5380.1) 5860.25,5393.37 ccw(c5860.25,5406.65) v1@5869.64,5397.26
  Bottom Layer w4: v1(5873.52,5393.37) 5897.52,5417.37 6140.86,5417.37 6373.52,5650.04 6415.52,5692.04 7101.84,5692.04 7159.84,5750.04 v1(7265.19,5750.04) ; v1@5873.52,5398.87 ccw(c5873.52,5412.15) 5882.91,5402.76 ccw(c5892.3,5393.37) v1@5879.02,5393.37 ; v1@5873.52,5402.87 ccw(c5873.52,5425.81) 5889.74,5409.59 ccw(c5905.96,5393.37) v1@5883.02,5393.37 ; v1@7258.47,5743.32 ccw(c7242.26,5727.11) 7242.26,5750.04 ccw(c7242.26,5772.98) v1@7258.47,5756.76 ; v1@7261.3,5746.15 ccw(c7251.91,5736.76) 7251.91,5750.04 ccw(c7251.91,5763.32) v1@7261.3,5753.93
RELAY.RELAY1: LED13.1 R125.1 U8.C10 | length 3809.7
  Top Layer w4: v1@5306.81,5144.66 ccw(c5290.59,5128.44) 5290.59,5151.37 ccw(c5290.59,5174.31) v1@5306.81,5158.09 ; v1@5309.64,5147.49 ccw(c5300.25,5138.1) 5300.25,5151.37 ccw(c5300.25,5164.65) v1@5309.64,5155.26 ; v1(5313.52,5151.37) 5231.37,5151.37 5214.36,5134.36 5214.36,5100 5217.7,5096.66 5217.7,4987.3 5240.9,4964.1 5240.9,4887.75 5228.34,4875.19 5228.34,4835 5228.34,4825.34 5228.34,4823.9 5224,4819.56 5224,4777.52 5228.34,4773.18 5228.34,4724.74 5228.34,4720 5228.34,4710 5228.34,4643.27 ; v1(5365.19,5325.04) 5351.33,5311.18 ; LED13.1@7226.62,5637.4 ccw(c7193.85,5670.17) 7240.19,5670.17 ; LED13.1@7229.45,5634.57 ccw(c7203.51,5660.51) 7240.19,5660.51 ; LED13.1@7232.27,5631.75 ccw(c7213.17,5650.86) 7240.19,5650.86 ; v1@7233.47,5693.32 cw(c7217.26,5677.11) 7240.19,5677.11 cw(c7263.13,5677.11) v1@7246.91,5693.32 ; v1@7236.3,5696.15 cw(c7226.91,5686.76) 7240.19,5686.76 cw(c7253.47,5686.76) v1@7244.08,5696.15 ; LED13.1@7239.12,5624.9 7240.19,5625.96 v1(7240.19,5700.04) ; 7240.19,5645.7 ccw(c7259.93,5645.7) LED13.1@7245.97,5631.75 ; 7240.19,5655.36 ccw(c7269.59,5655.36) LED13.1@7248.8,5634.57 ; 7240.19,5665.02 ccw(c7279.24,5665.02) LED13.1@7251.63,5637.4 ; 5228.34,4643.27 ccw(c5267.02,4643.27) 5239.67,4615.92 ; 5228.34,4643.27 ccw(c5267.02,4643.27) 5239.67,4615.92 ; 5239.67,4615.92 cw(c5227.14,4603.39) 5244.86,4603.39 ccw(c5227.14,4603.39) 5239.67,4615.92 ; 5239.67,4615.92 ccw(c5252.2,4628.45) 5252.2,4610.73 cw(c5252.2,4628.45) 5239.67,4615.92 ; 5342.39,5311.18 cw(c5342.39,5321.82) 5334.46,5314.73 ccw(c5342.39,5321.82) 5342.39,5311.18 ; 5342.38,5311.18 ccw(c5342.38,5300.54) 5334.46,5307.64 cw(c5342.39,5300.54) 5342.39,5311.18 ; 5351.33,5311.18 cw(c5351.33,5329.82) 5337.44,5317.39 ccw(c5351.33,5329.82) 5351.33,5311.18 ; 5351.33,5311.18 ccw(c5351.33,5292.54) 5337.44,5304.97 cw(c5351.33,5292.54) 5351.33,5311.18 ; 5351.33,5311.18 R125.1@5330,5311.18 5351.33,5311.18
  MidLayer1 w4: v1@5306.81,5158.09 ccw(c5290.59,5174.31) 5313.52,5174.31 ccw(c5336.46,5174.31) v1@5320.24,5158.09 ; v1@5309.64,5155.26 ccw(c5300.25,5164.65) 5313.52,5164.65 ccw(c5326.8,5164.65) v1@5317.41,5155.26 ; v1(5313.52,5151.37) 5313.52,5243.04 ; v1@5358.47,5318.32 cw(c5342.26,5302.11) 5365.19,5302.11 cw(c5388.13,5302.11) v1@5371.91,5318.32 ; v1@5361.3,5321.15 cw(c5351.91,5311.76) 5365.19,5311.76 cw(c5378.47,5311.76) v1@5369.08,5321.15 ; v1(5365.19,5325.04) 5365.19,5294.71 ; 5313.52,5243.04 5365.19,5294.71 ; 5313.52,5243.04 5365.19,5294.71
  Bottom Layer w4: v1(5365.19,5325.04) 5406.86,5366.71 5884.84,5366.71 5919.5,5401.37 6147.69,5401.37 6422.35,5676.04 7123.96,5676.04 7160,5640 7205,5640 7240.19,5675.19 v1(7240.19,5700.04) ; v1@5365.19,5330.54 ccw(c5365.19,5343.82) 5374.58,5334.43 ccw(c5383.97,5325.04) v1@5370.69,5325.04 ; v1@5365.19,5334.54 ccw(c5365.19,5357.48) 5381.41,5341.26 ccw(c5397.63,5325.04) v1@5374.69,5325.04 ; v1@7233.47,5693.32 cw(c7217.26,5677.11) 7240.19,5677.11 cw(c7263.13,5677.11) v1@7246.91,5693.32 ; v1@7236.3,5696.15 cw(c7226.91,5686.76) 7240.19,5686.76 cw(c7253.47,5686.76) v1@7244.08,5696.15
RELAY.RELAY2: LED14.1 R127.1 U8.C12 | length 3587.9
  Top Layer w4: v1(5277.52,5183.37) 5336.52,5183.37 5348.52,5171.37 5348.52,5035 5348.52,5010.75 5355.19,5004.08 5355.19,4941.71 5355.19,4930 5355.19,4865.1 5363.5,4856.79 5363.5,4820 5350.5,4807 5337.11,4807 5307.08,4776.97 5307.08,4724.74 5307.08,4720 5307.08,4710 5307.08,4643.27 ccw(c5345.76,4643.27) 5318.41,4615.92 ; v1@5281.41,5179.49 cw(c5290.8,5170.1) 5290.8,5183.37 cw(c5290.8,5196.65) v1@5281.41,5187.26 ; v1@5284.24,5176.66 cw(c5300.46,5160.44) 5300.46,5183.37 cw(c5300.46,5206.31) v1@5284.24,5190.09 ; U8.C12@5323.6,4603.39 ccw(c5305.88,4603.39) 5318.41,4615.92 ; U8.C12@5330.94,4610.73 cw(c5330.94,4628.45) 5318.41,4615.92 ; v1(5876.86,5333.37) 5876.86,5319.18 5884.86,5311.18 R127.1@5910,5311.18 ; R127.1@5902.92,5304.59 ccw(c5887.01,5288.68) 5887.01,5311.18 ccw(c5887.01,5333.68) R127.1@5902.92,5317.77 ; R127.1@5905.75,5307.42 ccw(c5896.67,5298.34) 5896.67,5311.18 ccw(c5896.67,5324.02) R127.1@5905.75,5314.94 ; LED14.1@7239.12,5454.51 7242.99,5458.37 v1(7298.52,5458.37) ; LED14.1@7243.14,5450.49 cw(c7262.18,5431.46) 7262.18,5458.37 ; LED14.1@7245.97,5447.66 cw(c7271.83,5421.8) 7271.83,5458.37 ; LED14.1@7248.8,5444.83 cw(c7281.49,5412.14) 7281.49,5458.37 ; LED14.1@7248.8,5464.19 ccw(c7262.83,5478.22) 7262.83,5458.37 ; LED14.1@7251.63,5442.01 cw(c7291.15,5402.49) v1@7291.15,5458.37 ; LED14.1@7251.63,5467.02 ccw(c7272.49,5487.88) 7272.49,5458.37 ; v1@7291.81,5451.66 ccw(c7275.59,5435.44) 7275.59,5458.37 ccw(c7275.59,5481.31) v1@7291.81,5465.09 ; v1@7294.64,5454.49 ccw(c7285.25,5445.1) 7285.25,5458.37 ccw(c7285.25,5471.65) v1@7294.64,5462.26
  MidLayer2 w4: v1@5270.81,5190.09 ccw(c5254.59,5206.31) 5277.52,5206.31 ccw(c5300.46,5206.31) v1@5284.24,5190.09 ; v1@5273.64,5187.26 ccw(c5264.25,5196.65) 5277.52,5196.65 ccw(c5290.8,5196.65) v1@5281.41,5187.26 ; v1(5277.52,5183.37) 5277.52,5215.37 5362.19,5300.04 5431.86,5300.04 5465.19,5333.37 v1(5876.86,5333.37) ; v1@5870.14,5326.66 ccw(c5853.92,5310.44) 5853.92,5333.37 ccw(c5853.92,5356.31) v1@5870.14,5340.09 ; v1@5872.97,5329.49 ccw(c5863.58,5320.1) 5863.58,5333.37 ccw(c5863.58,5346.65) v1@5872.97,5337.26
  Bottom Layer w4: v1(5876.86,5333.37) 7141.77,5333.37 7157.94,5317.21 7177.21,5317.21 7215.54,5355.54 7270.54,5355.54 7298.52,5383.52 v1(7298.52,5458.37) ; v1@5880.75,5329.49 cw(c5890.14,5320.1) 5890.14,5333.37 cw(c5890.14,5346.65) v1@5880.75,5337.26 ; v1@5883.57,5326.66 cw(c5899.79,5310.44) 5899.79,5333.37 cw(c5899.79,5356.31) v1@5883.57,5340.09 ; v1@7291.81,5451.66 cw(c7275.59,5435.44) 7298.52,5435.44 cw(c7321.46,5435.44) v1@7305.24,5451.66 ; v1@7294.64,5454.49 cw(c7285.25,5445.1) 7298.52,5445.1 cw(c7311.8,5445.1) v1@7302.41,5454.49
RELAY.RELAY3: LED15.1 R129.1 U8.B12 | length 3017.7
  Top Layer w4: U8.B12@5323.6,4642.76 ccw(c5305.88,4642.76) 5318.41,4655.29 ; U8.B12@5330.94,4650.1 cw(c5330.94,4667.83) 5318.41,4655.29 ; 5361.45,4806.63 5353.81,4799 ; v1@5364.02,5175.04 cw(c5341.09,5175.04) 5357.31,5158.82 cw(c5373.52,5142.61) v1@5373.52,5165.54 ; v1@5368.02,5175.04 cw(c5354.75,5175.04) 5364.13,5165.65 cw(c5373.52,5156.26) v1@5373.52,5169.54 ; v1(5373.52,5175.04) 5356.86,5158.37 5356.86,5025 5356.86,5013.73 5363.19,5007.39 5363.19,4966.71 5363.19,4950 5363.19,4868.41 5371.5,4860.1 5371.5,4816.69 5353.81,4799 ; R129.1@6505,5311.18 6523.86,5311.18 ; R129.1@6513.01,5305.68 cw(c6523.86,5297.74) 6523.86,5311.18 ; R129.1@6513.01,5316.68 ccw(c6523.86,5324.62) 6523.86,5311.18 ; 6522.54,5312.49 cw(c6509.85,5299.8) v1@6526.7,5293.61 ; 6526.97,5308.07 cw(c6516.32,5297.43) v1@6530.45,5292.23 ; 6531.39,5303.65 cw(c6522.79,5295.05) v1@6534.2,5290.84 ; v1(6531.86,5291.71) 6531.86,5303.18 6523.86,5311.18 ; v1(7231.86,5333.37) 7231.86,5318.64 7239.12,5311.37 ; LED15.1@7231.92,5300.28 ccw(c7226.97,5311.37) 7239.12,5311.37 ; LED15.1@7233.55,5296.62 ccw(c7229.72,5305.21) 7239.12,5305.21 ccw(c7248.53,5305.21) LED15.1@7244.7,5296.62 ; LED15.1@7239.12,5284.12 7239.12,5311.37 ; LED15.1@7246.33,5300.28 cw(c7251.27,5311.37) 7239.12,5311.37 ; 5318.41,4655.29 cw(c5325.59,4662.47) 5315.44,4662.47 5315.44,4710 5315.44,4720 5315.44,4724.74 5315.44,4774.01 5340.42,4799 5353.81,4799
  Bottom Layer w4: v1(5373.52,5175.04) 5506.86,5308.37 5513.98,5315.5 5900,5315.5 5909.87,5325.37 6498.19,5325.37 v1(6531.86,5291.71) 6565.19,5325.04 7138.79,5325.04 7156.84,5307 7205.48,5307 v1(7231.86,5333.37) ; v1@6522.36,5291.71 ccw(c6499.42,5291.71) 6515.64,5307.93 ccw(c6531.86,5324.14) 6531.86,5301.21 ccw(c6531.86,5324.14) 6548.07,5307.93 ccw(c6564.29,5291.71) v1@6541.36,5291.71 ; v1@6526.36,5291.71 ccw(c6513.08,5291.71) 6522.47,5301.1 ccw(c6531.86,5310.49) 6531.86,5297.21 ccw(c6531.86,5310.49) 6541.25,5301.1 ccw(c6550.64,5291.71) v1@6537.36,5291.71 ; v1@7222.36,5333.37 cw(c7199.42,5333.37) 7215.64,5317.16 cw(c7231.86,5300.94) v1@7231.86,5323.87 ; v1@7226.36,5333.37 cw(c7213.08,5333.37) 7222.47,5323.99 cw(c7231.86,5314.6) v1@7231.86,5327.87
RELAYS#.C0: J14.2 RLY1.3 RLY1.6 | length 872.6
  Top Layer w30: J14.2@4999.71,5880 ccw(c5071.45,5880) 5020.72,5829.28 ; J14.2@5003.37,5880 5003.37,5846.63 5167.6,5682.4 RLY1.6@5167.6,5481.22 RLY1.3@5167.6,5245 ; J14.2@5029.71,5880 ccw(c5173.87,5880) 5071.94,5778.06
RELAYS#.C1: J14.5 RLY2.3 RLY2.6 | length 796.5
  Top Layer w30: J14.5@5593.93,5853.66 cw(c5593.93,5790.07) 5638.89,5835.04 cw(c5683.85,5880) J14.5@5620.26,5880 ; J14.5@5593.93,5880 5742.6,5731.33 RLY2.6@5742.6,5481.22 RLY2.3@5742.6,5245
RELAYS#.C2: J14.8 RLY3.3 RLY3.6 | length 800.4
  Top Layer w30: J14.8@6184.48,5853.66 cw(c6184.48,5790.07) 6229.44,5835.04 cw(c6274.4,5880) J14.8@6210.82,5880 ; J14.8@6184.48,5880 6342.6,5721.88 RLY3.6@6342.6,5481.22 RLY3.3@6342.6,5245
RELAYS#.C3: J14.11 RLY4.3 RLY4.6 | length 895.4
  Top Layer w30: J14.11@6775.03,5880 6775.03,5824.97 ; RLY4.3@6922.6,5245 RLY4.6@6922.6,5481.22 6922.6,5747.4 6860,5810 6790,5810 6775.03,5824.97 ; 6775.03,5824.98 cw(c6819.34,5824.98) 6791.55,5859.49 ccw(c6819.34,5824.98) 6775.03,5824.98 ; 6775.03,5824.98 ccw(c6730.72,5824.98) 6758.51,5859.49 cw(c6730.72,5824.98) 6775.03,5824.98
RELAYS#.NC0: J14.1 RLY1.2 RLY1.7 | length 930.6
  Top Layer w30: J14.1@4787.9,5861.38 cw(c4742.94,5816.41) 4806.52,5816.41 cw(c4870.11,5816.41) J14.1@4825.15,5861.38 ; J14.1@4806.52,5880 4806.52,5768.48 4855,5720 4995,5720 5035,5680 5035,5510 5072.38,5472.62 5080.98,5464.02 RLY1.2@5080.98,5245
RELAYS#.NC1: J14.4 RLY2.2 RLY2.7 | length 944.6
  Top Layer w30: J14.4@5378.45,5861.38 cw(c5333.49,5816.41) 5397.07,5816.41 cw(c5460.66,5816.41) J14.4@5415.7,5861.38 ; J14.4@5397.08,5880 5397.08,5732.92 5445,5685 5620,5685 5655.98,5649.02 RLY2.7@5655.98,5481.22 RLY2.2@5655.98,5245
RELAYS#.NC2: J14.7 RLY3.2 RLY3.7 | length 846
  Top Layer w30: J14.7@5987.63,5853.66 cw(c5987.63,5790.07) 6032.59,5835.04 cw(c6077.55,5880) J14.7@6013.96,5880 ; J14.7@5987.63,5880 6255.98,5611.64 RLY3.7@6255.98,5481.22 RLY3.2@6255.98,5245
RELAYS#.NC3: J14.10 RLY4.2 RLY4.7 | length 950
  Top Layer w30: J14.10@6559.55,5861.38 cw(c6514.59,5816.41) 6578.18,5816.41 cw(c6641.76,5816.41) J14.10@6596.8,5861.38 ; J14.10@6578.18,5880 6578.18,5781.82 6620,5740 6805,5740 6835.98,5709.02 RLY4.7@6835.98,5481.22 RLY4.2@6835.98,5245
RELAYS#.NO0: J14.3 RLY1.4 RLY1.5 | length 757.2
  Top Layer w30: J14.3@5181.6,5861.38 cw(c5136.64,5816.41) 5200.22,5816.41 cw(c5263.81,5816.41) J14.3@5218.85,5861.38 ; J14.3@5200.22,5880 5200.22,5778.99 5254.21,5725 RLY1.5@5254.21,5481.22 RLY1.4@5254.21,5245
RELAYS#.NO1: J14.6 RLY2.4 RLY2.5 | length 750.8
  Top Layer w30: J14.6@5772.15,5861.38 cw(c5727.19,5816.41) 5790.78,5816.41 cw(c5854.36,5816.41) J14.6@5809.4,5861.38 ; J14.6@5790.78,5880 5790.78,5808.44 5829.21,5770 RLY2.5@5829.21,5481.22 RLY2.4@5829.21,5245
RELAYS#.NO2: J14.9 RLY3.4 RLY3.5 | length 754.7
  Top Layer w30: J14.9@6362.7,5861.38 cw(c6317.74,5816.41) 6381.33,5816.41 cw(c6444.91,5816.41) J14.9@6399.95,5861.38 ; J14.9@6381.33,5880 6381.33,5790 6429.21,5742.11 RLY3.5@6429.21,5481.22 RLY3.4@6429.21,5245
RELAYS#.NO3: J14.12 RLY4.4 RLY4.5 | length 750.3
  Top Layer w30: J14.12@6953.25,5861.38 cw(c6908.29,5816.41) 6971.88,5816.41 cw(c7035.47,5816.41) J14.12@6990.5,5861.38 ; J14.12@6971.88,5880 6971.88,5798.12 7009.21,5760.79 RLY4.5@7009.21,5481.22 RLY4.4@7009.21,5245
RS232.CTS: R210.1 U8.J2 | length 5393.6
  Top Layer w4: v1@4514.29,4427.37 cw(c4519.44,4414.08) 4529.53,4424.16 ; v1@4515.73,4423.64 cw(c4521.87,4407.82) 4533.87,4419.82 ; v1@4525.21,4425.04 v1(4515.19,4425.04) 4528.65,4425.04 4535.82,4417.87 4750,4417.87 4767.39,4417.87 4802.58,4382.67 4807.58,4382.67 4820,4382.67 4855.26,4382.67 4860,4382.67 4870,4382.67 4917.53,4382.67 cw(c4917.53,4372.52) 4924.71,4379.7 ; U8.J2@4929.9,4367.17 ccw(c4912.17,4367.17) 4924.71,4379.7 ; U8.J2@4937.24,4374.51 cw(c4937.24,4392.23) 4924.71,4379.7
  MidLayer2 w4: v1@619.19,5160.87 cw(c619.19,5137.94) 635.41,5154.16 cw(c651.63,5170.37) v1@628.69,5170.37 ; v1@619.19,5164.87 cw(c619.19,5151.6) 628.58,5160.99 cw(c637.97,5170.37) v1@624.69,5170.37 ; v1(619.19,5170.37) 665.02,5124.54 1330.48,5124.54 1330.98,5125.04 1673.52,5125.04 1781.86,5016.71 3723.52,5016.71 3956.86,4783.37 4281.86,4783.37 4515.19,4550.04 v1(4515.19,4425.04) ; v1@4508.47,4431.76 ccw(c4492.26,4447.98) 4515.19,4447.98 ccw(c4538.13,4447.98) v1@4521.91,4431.76 ; v1@4511.3,4428.93 ccw(c4501.91,4438.32) 4515.19,4438.32 ccw(c4528.47,4438.32) v1@4519.08,4428.93
  Bottom Layer w4: R210.1@489.34,5413 cw(c473.43,5397.09) 495.93,5397.09 cw(c518.43,5397.09) R210.1@502.52,5413 ; R210.1@492.17,5415.82 cw(c483.09,5406.74) 495.93,5406.74 cw(c508.77,5406.74) R210.1@499.69,5415.82 ; R210.1@495.93,5420.08 495.93,5380.93 479.63,5364.63 479.63,5195 504.25,5170.37 v1(619.19,5170.37) v1@615.19,5174.37 ; v1@612.47,5163.66 ccw(c596.26,5147.44) 596.26,5170.37 ccw(c596.26,5193.31) v1@612.47,5177.09 ; v1@615.3,5166.49 ccw(c605.91,5157.1) 605.91,5170.37 ccw(c605.91,5183.65) v1@615.3,5174.26
RS232.RTS: U8.E3 U59.10 | length 6278.2
  Top Layer w4: v1@4540.19,5098.87 cw(c4540.19,5075.94) 4556.41,5092.16 cw(c4572.63,5108.37) v1@4549.69,5108.37 ; v1@4540.19,5102.87 cw(c4540.19,5089.6) 4549.58,5098.99 cw(c4558.97,5108.37) v1@4545.69,5108.37 ; v1(4540.19,5108.37) 4565.19,5083.37 4565.19,4816.71 4656.86,4725.04 4656.86,4586.36 4680.5,4562.71 4832.19,4562.71 4846.39,4548.51 4855.26,4548.51 4860,4548.51 4870,4548.51 4936.73,4548.51 ; 4936.73,4548.51 cw(c4936.73,4509.83) 4964.08,4537.18 ; 4936.73,4548.51 cw(c4936.73,4509.83) 4964.08,4537.18 ; 4964.08,4537.18 ccw(c4976.61,4549.71) 4976.61,4531.99 cw(c4976.61,4549.71) 4964.08,4537.18 ; 4964.08,4537.18 cw(c4951.55,4524.65) 4969.27,4524.65 ccw(c4951.55,4524.65) 4964.08,4537.18
  MidLayer1 w4: v1(380,5460) 445,5460 450,5455 v4(532.81,5455) ; v1@383.89,5456.11 cw(c393.28,5446.72) 393.28,5460 cw(c393.28,5473.28) v1@383.89,5463.89 ; v1@386.72,5453.28 cw(c402.93,5437.06) 402.93,5460 cw(c402.93,5482.93) v1@386.72,5466.72 ; v4@525.87,5448.06 ccw(c509.13,5431.31) 509.13,5455 ccw(c509.13,5478.69) v4@525.87,5461.94 ; v4@528.7,5450.89 ccw(c518.78,5440.97) 518.78,5455 ccw(c518.78,5469.03) v4@528.7,5459.11
  MidLayer2 w4: v1(380,5460) 406.19,5486.19 406.19,5527.5 469.55,5590.86 1869.14,5590.86 1905,5555 ; v1@380,5465.5 ccw(c380,5478.78) 389.39,5469.39 ccw(c398.78,5460) v1@385.5,5460 ; v1@380,5469.5 ccw(c380,5492.43) 396.22,5476.22 ccw(c412.43,5460) v1@389.5,5460 ; 1870,5590 1905,5555 ; v1@4530.69,5108.37 ccw(c4507.76,5108.37) 4523.97,5124.59 ccw(c4540.19,5140.81) v1@4540.19,5117.87 ; v1@4534.69,5108.37 ccw(c4521.41,5108.37) 4530.8,5117.76 ccw(c4540.19,5127.15) v1@4540.19,5113.87 ; v1(4540.19,5108.37) 4506.86,5141.71 3431.67,5141.71 3347,5226.37 3347,5298 3336.86,5308.14 3182.09,5308.14 3031.86,5458.37 2545.54,5458.37 2516.38,5487.54 2212.54,5487.54 2206.88,5481.88 2133.7,5481.88 2092.77,5522.81 2007.19,5522.81 1975,5555 1905,5555
  Bottom Layer w4: v4(532.81,5455) 540,5455 560.08,5455 595,5420.08 U59.10@704.59,5420.08 ; v4@536.92,5450.89 cw(c546.84,5440.97) 546.84,5455 cw(c546.84,5469.03) v4@536.92,5459.11 ; v4@539.75,5448.06 cw(c556.5,5431.31) 556.5,5455 cw(c556.5,5478.69) v4@539.75,5461.94 ; U59.10@674.61,5411.75 ccw(c654.5,5391.64) 654.5,5420.08 ccw(c654.5,5448.52) U59.10@674.61,5428.41 ; U59.10@677.44,5414.58 ccw(c664.16,5401.3) 664.16,5420.08 ccw(c664.16,5438.86) U59.10@677.44,5425.58
RS232.RXD: R209.1 U8.G2 | length 5604.1
  Top Layer w4: v1@4615.19,4490.54 cw(c4615.19,4467.61) 4631.41,4483.82 cw(c4647.63,4500.04) v1@4624.69,4500.04 ; v1@4615.19,4491.71 v1(4615.19,4500.04) 4657.36,4457.87 4769,4457.87 4783.95,4457.87 4787.45,4461.37 4797.69,4461.37 4819,4461.37 4848.52,4461.37 ; v1@4615.19,4494.54 cw(c4615.19,4481.26) 4624.58,4490.65 cw(c4633.97,4500.04) v1@4620.69,4500.04 ; 4848.52,4461.41 4851.26,4461.41 4855.26,4461.41 4860,4461.41 4870,4461.41 4917.53,4461.41 ; 4917.53,4461.41 cw(c4917.53,4451.26) 4924.71,4458.44 ; 4917.53,4461.41 cw(c4917.53,4451.26) 4924.71,4458.44 ; 4924.71,4458.44 cw(c4912.17,4445.91) 4929.9,4445.91 ccw(c4912.17,4445.91) 4924.71,4458.44 ; 4924.71,4458.44 ccw(c4937.24,4470.97) 4937.24,4453.25 cw(c4937.24,4470.97) 4924.71,4458.44
  Bottom Layer w4: R209.1@489.34,5558 cw(c473.43,5542.09) 495.93,5542.09 cw(c518.43,5542.09) R209.1@502.52,5558 ; R209.1@492.17,5560.82 cw(c483.09,5551.74) 495.93,5551.74 cw(c508.77,5551.74) R209.1@499.69,5560.82 ; R209.1@495.93,5565.08 495.93,5540 515,5520.93 515,5355 536.63,5333.37 701.63,5333.37 715.52,5319.48 715.52,5065 737.71,5042.81 1247.38,5042.81 1256.81,5033.37 1323.52,5033.37 1353.66,5003.24 1373.36,4983.54 3812.3,4983.54 3821.29,4974.54 3868.23,4974.54 3891.69,4998 4087.19,4998 4097.81,4987.38 4097.81,4972.19 4286.29,4783.71 4598.19,4783.71 4648.52,4733.37 4648.52,4533.37 v1(4615.19,4500.04) ; v1@4615.19,4505.54 ccw(c4615.19,4518.82) 4624.58,4509.43 ccw(c4633.97,4500.04) v1@4620.69,4500.04 ; v1@4615.19,4509.54 ccw(c4615.19,4532.48) 4631.41,4516.26 ccw(c4647.63,4500.04) v1@4624.69,4500.04
RS232.TXD: U8.B1 U59.11 | length 5035.1
  Top Layer w4: v1@4743.86,4745.21 cw(c4743.86,4722.27) 4760.07,4738.49 cw(c4776.29,4754.71) v1@4753.36,4754.71 ; v1@4743.86,4749.21 cw(c4743.86,4735.93) 4753.25,4745.32 cw(c4762.64,4754.71) v1@4749.36,4754.71 ; v1(4743.86,4754.71) 4825,4673.56 4825,4660 4842.24,4642.76 4860,4642.76 4870,4642.76 U8.B1@4897.87,4642.76 ; U8.B1@4892.57,4637.45 ccw(c4879.77,4624.65) 4879.77,4642.76 ccw(c4879.77,4660.86) U8.B1@4892.57,4648.06 ; U8.B1@4892.68,4637.56 ccw(c4880.15,4625.03) 4880.15,4642.76 ccw(c4880.15,4660.48) U8.B1@4892.68,4647.95
  Bottom Layer w4: U59.11@700.52,5470 745,5470 ; U59.11@736.82,5464.9 cw(c745,5460.9) 745,5470 ; U59.11@736.89,5475.13 ccw(c745,5478.98) 745,5470 ; v1@4734.36,4754.71 ccw(c4711.42,4754.71) 4727.64,4770.93 ccw(c4743.86,4787.14) v1@4743.86,4764.21 ; v1@4738.36,4754.71 ccw(c4725.08,4754.71) 4734.47,4764.1 ccw(c4743.86,4773.49) v1@4743.86,4760.21 ; v1(4743.86,4754.71) 4715.19,4783.37 4640.19,4783.37 4631.86,4791.71 4290.19,4791.71 4105.81,4976.09 4105.81,4990.69 4090.5,5006 3888.37,5006 3864.91,4982.54 3824.61,4982.54 3815.61,4991.54 1376.68,4991.54 1326.01,5042.2 1259.3,5042.2 1250.69,5050.81 742.71,5050.81 723.52,5070 723.52,5323.52 750,5350 750,5465 745,5470
RS232_C1+: C148.1 U59.1 | length 305
  Bottom Layer w4: U59.1@929,5720.08 1019.92,5720.08 1029.92,5710.08 C148.1@1096.44,5710.08 ; U59.1@956.15,5714.58 cw(c969.43,5701.3) 969.43,5720.08 cw(c969.43,5738.86) U59.1@956.15,5725.58 ; U59.1@958.98,5711.75 cw(c979.09,5691.64) 979.09,5720.08 cw(c979.09,5748.52) U59.1@958.98,5728.41 ; C148.1@1089.5,5703.14 ccw(c1072.76,5686.39) 1072.76,5710.08 ccw(c1072.76,5733.76) C148.1@1089.5,5717.01 ; C148.1@1092.33,5705.97 ccw(c1082.41,5696.05) 1082.41,5710.08 ccw(c1082.41,5724.11) C148.1@1092.33,5714.19
RS232_C1-: C148.2 U59.3 | length 420.5
  Bottom Layer w4: U59.3@929,5620.08 1117.86,5620.08 1137.78,5640 C148.2@1137.78,5710.08 ; U59.3@956.15,5614.58 cw(c969.43,5601.3) 969.43,5620.08 cw(c969.43,5638.86) U59.3@956.15,5625.58 ; U59.3@958.98,5611.75 cw(c979.09,5591.64) 979.09,5620.08 cw(c979.09,5648.52) U59.3@958.98,5628.41 ; C148.2@1130.84,5703.14 cw(c1114.09,5686.39) 1137.78,5686.39 cw(c1161.47,5686.39) C148.2@1144.72,5703.14 ; C148.2@1133.67,5705.97 cw(c1123.75,5696.05) 1137.78,5696.05 cw(c1151.81,5696.05) C148.2@1141.89,5705.97
RS232_C2+: C150.1 U59.4 | length 302.9
  Bottom Layer w4: U59.4@929,5570.08 1024.92,5570.08 1029.92,5565.08 C150.1@1096.44,5565.08 ; U59.4@956.15,5564.58 cw(c969.43,5551.3) 969.43,5570.08 cw(c969.43,5588.86) U59.4@956.15,5575.58 ; U59.4@958.98,5561.75 cw(c979.09,5541.64) 979.09,5570.08 cw(c979.09,5598.52) U59.4@958.98,5578.41 ; C150.1@1089.5,5558.14 ccw(c1072.76,5541.39) 1072.76,5565.08 ccw(c1072.76,5588.76) C150.1@1089.5,5572.01 ; C150.1@1092.33,5560.97 ccw(c1082.41,5551.05) 1082.41,5565.08 ccw(c1082.41,5579.11) C150.1@1092.33,5569.19
RS232_C2-: C150.2 U59.5 | length 382.7
  Bottom Layer w4: U59.5@929,5520.08 1130.08,5520.08 1137.78,5527.78 C150.2@1137.78,5565.08 ; U59.5@956.15,5514.58 cw(c969.43,5501.3) 969.43,5520.08 cw(c969.43,5538.86) U59.5@956.15,5525.58 ; U59.5@958.98,5511.75 cw(c979.09,5491.64) 979.09,5520.08 cw(c979.09,5548.52) U59.5@958.98,5528.41 ; C150.2@1130.84,5558.14 cw(c1114.09,5541.39) 1137.78,5541.39 cw(c1161.47,5541.39) C150.2@1144.72,5558.14 ; C150.2@1133.67,5560.97 cw(c1123.75,5551.05) 1137.78,5551.05 cw(c1151.81,5551.05) C150.2@1141.89,5560.97
RS232_CTS#: R210.2 U59.9 | length 310.6
  Bottom Layer w4: R210.2@538.29,5410.27 cw(c538.29,5382.64) 557.82,5402.18 ; R210.2@538.29,5414.27 cw(c538.29,5396.3) 551,5409 ; R210.2@538.29,5420.08 539.92,5420.08 589.92,5370.08 U59.9@704.59,5370.08 ; R210.2@547.61,5419.59 ccw(c564.98,5419.59) 552.7,5407.3 ; U59.9@674.61,5361.75 ccw(c654.5,5341.64) 654.5,5370.08 ccw(c654.5,5398.52) U59.9@674.61,5378.41 ; U59.9@677.44,5364.58 ccw(c664.16,5351.3) 664.16,5370.08 ccw(c664.16,5388.86) U59.9@677.44,5375.58
RS232_RX#: R209.2 U59.12 | length 314.6
  Bottom Layer w4: R209.2@538.29,5555.27 cw(c538.29,5531.58) 555.04,5548.33 ; R209.2@538.29,5559.27 cw(c538.29,5545.24) R209.2@548.21,5555.16 ; R209.2@538.29,5565.08 583.29,5520.08 U59.12@704.59,5520.08 ; R209.2@543.61,5564.59 ccw(c555.26,5564.59) R209.2@547.02,5556.35 ; R209.2@547.61,5564.59 ccw(c568.92,5564.59) 553.85,5549.52 ; U59.12@674.61,5511.75 ccw(c654.5,5491.64) 654.5,5520.08 ccw(c654.5,5548.52) U59.12@674.61,5528.41 ; U59.12@677.44,5514.58 ccw(c664.16,5501.3) 664.16,5520.08 ccw(c664.16,5538.86) U59.12@677.44,5525.58
RS232_V+: C149.2 U59.2 | length 542.2
  Bottom Layer w4: C149.2@537.78,5710.08 593.76,5710.08 608.84,5695 785,5695 810,5670 U59.2@930,5670 ; C149.2@541.89,5705.97 cw(c551.81,5696.05) 551.81,5710.08 cw(c551.81,5724.11) C149.2@541.89,5714.19 ; C149.2@544.72,5703.14 cw(c561.47,5686.39) 561.47,5710.08 cw(c561.47,5733.76) C149.2@544.72,5717.01 ; 878.72,5670 ccw(c878.72,5698.7) U59.2@899.02,5678.41 ; 879.1,5670 cw(c879.1,5641.83) U59.2@899.02,5661.75 ; 888.38,5670 ccw(c888.38,5689.05) U59.2@901.85,5675.58 ; 888.75,5670 cw(c888.75,5651.48) U59.2@901.85,5664.58
RS232_V-: C151.1 U59.6 | length 277
  Bottom Layer w4: U59.6@929,5470.08 1029.92,5470.08 1040,5460 1040,5435 1054.92,5420.08 C151.1@1096.44,5420.08 ; U59.6@956.15,5464.58 cw(c969.43,5451.3) 969.43,5470.08 cw(c969.43,5488.86) U59.6@956.15,5475.58 ; U59.6@958.98,5461.75 cw(c979.09,5441.64) 979.09,5470.08 cw(c979.09,5498.52) U59.6@958.98,5478.41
